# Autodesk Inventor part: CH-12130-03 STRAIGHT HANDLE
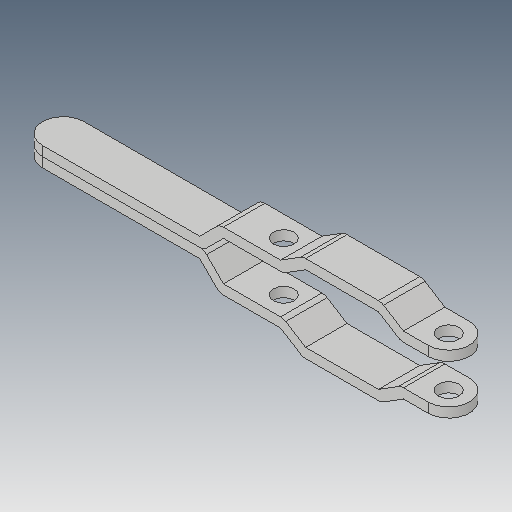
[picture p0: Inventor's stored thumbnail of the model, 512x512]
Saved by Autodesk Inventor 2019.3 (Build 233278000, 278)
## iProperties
Created: 2012-09
Part Number: CH-12130-03 STRAIGHT HANDLE
Material: Ogólny
Document SubType Name: Modeling
Designer: CADENGINEERING4
Density: 1 g/cm^3
Appearance: Domyślna
Author: CADENGINEERING4
Revision Number: ÈÎºÎ
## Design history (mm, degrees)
feature "ÇÐ³ý-À­Éì1"
feature "¾µÏò1"
node "Bryła1"
node "Bryła2"
